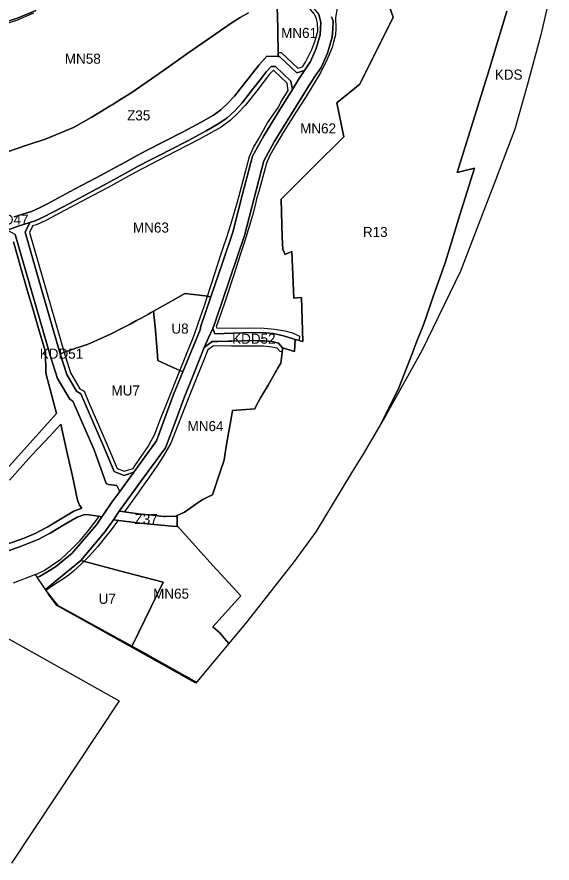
# Model space of a CAD drawing. Extents: x 7428841 to 7433518, y 5545054 to 5546840.
# Drawn here: x 7432924 to 7433454, y 5545245 to 5546085 of the extents above; entities that cross this region are included whole.
import ezdxf

# ---------------------------------------------------------------- set-up
doc = ezdxf.new("R2010")
doc.units = 0
for name, color, linetype in [('linie_rozgraniczajace', 7, 'Continuous'), ('linie_zabudowy_nieprzekraczalne', 7, 'Continuous'), ('oznaczenia_przeznaczen', 7, 'Continuous')]:
    doc.layers.add(name, color=color, linetype=linetype)

msp = doc.modelspace()

# ---------------------------------------------------------------- linework, layer by layer
at = {"layer": 'linie_rozgraniczajace'}
for points in [[(7433454.3, 5546115.72), (7433443.19, 5546066.88), (7433429.63, 5546016.49), (7433417.27, 5545973.13), (7433398.05, 5545922.73), (7433363.46, 5545832.41), (7433325.3, 5545753.97), (7433290.23, 5545690.46), (7433285.41, 5545682.3), (7433302.34, 5545716.55), (7433314.27, 5545746.9), (7433320.28, 5545762.8), (7433326.2, 5545777.24), (7433328.95, 5545785.66), (7433335.99, 5545806.26), (7433348.47, 5545841.54), (7433362.88, 5545888.07), (7433377.29, 5545934.6), (7433360.23, 5545930.2), (7433374.37, 5545975.87), (7433391.5, 5546031.17), (7433400.97, 5546061.74), (7433409.6, 5546090.32)], [(7433181.74, 5546094.87), (7433182.26, 5546073.37), (7433182.64, 5546045.32), (7433171.51, 5546045.51), (7433163.49, 5546036.88), (7433150.31, 5546019.98), (7433139.24, 5546005.8), (7433132.53, 5545998.52), (7433125.84, 5545992.31), (7433118.43, 5545987.1), (7433106.43, 5545980.19), (7433088.4, 5545970.56), (7433070.16, 5545961.15), (7433051.49, 5545951.53), (7433039.13, 5545945.15), (7433030.77, 5545940.55), (7433021.62, 5545935.53), (7433007.22, 5545927.61), (7432975.83, 5545910.91), (7432953.83, 5545899.22), (7432946.61, 5545895.38), (7432937.92, 5545891.47), (7432920.69, 5545886.06)], [(7433409.6, 5546090.32), (7433400.97, 5546061.74), (7433391.5, 5546031.17), (7433374.37, 5545975.87), (7433360.23, 5545930.2), (7433377.29, 5545934.6), (7433362.88, 5545888.07), (7433348.47, 5545841.54), (7433335.99, 5545806.26), (7433328.95, 5545785.66), (7433326.2, 5545777.24), (7433320.28, 5545762.8), (7433314.27, 5545746.9), (7433302.34, 5545716.55), (7433285.41, 5545682.3), (7433267.11, 5545651.33), (7433255.38, 5545631.97), (7433220.04, 5545573.5), (7433198.54, 5545544.11), (7433151.43, 5545484.12), (7433133.63, 5545462.68), (7433129.14, 5545467.92), (7433124.66, 5545473.16), (7433118, 5545479.19), (7433145.55, 5545510.1), (7433117.88, 5545540.1), (7433103.27, 5545556.46), (7433082.99, 5545578.82), (7433082.39, 5545578.86), (7433082.56, 5545589.65), (7433089.8, 5545593.1), (7433098.8, 5545599.43), (7433103.3, 5545602.59), (7433107.8, 5545605.75), (7433112.61, 5545608.07), (7433117.43, 5545610.39), (7433125.35, 5545633.94), (7433128.65, 5545643.77), (7433128.92, 5545644.9), (7433131.19, 5545658.13), (7433133.46, 5545671.37), (7433135.62, 5545683.94), (7433137.36, 5545694.08), (7433159.36, 5545695.62), (7433160.41, 5545698.08), (7433165.26, 5545706.45), (7433172.71, 5545719.26), (7433180.15, 5545732.08), (7433181.14, 5545733.79), (7433182.13, 5545735.49), (7433185.37, 5545740.86), (7433186.45, 5545751.57), (7433186.9, 5545756.06), (7433198.7, 5545752.45), (7433199.64, 5545764.59), (7433207.09, 5545762.29), (7433206.38, 5545784.21), (7433205.66, 5545806.13), (7433198.05, 5545805.51), (7433196.13, 5545851.62), (7433193.15, 5545850.35), (7433190.71, 5545849.47), (7433189.29, 5545848.96), (7433189.14, 5545849.48), (7433187.38, 5545854.17), (7433186.46, 5545865.63), (7433185.67, 5545903.81), (7433216.66, 5545934.69), (7433247.64, 5545965.57), (7433240.95, 5545999.33), (7433263.56, 5546017.81), (7433296.79, 5546084.2), (7433292.83, 5546095.75)], [(7433292.83, 5546095.75), (7433296.79, 5546084.2), (7433263.56, 5546017.81), (7433240.95, 5545999.33), (7433247.64, 5545965.57), (7433216.66, 5545934.69), (7433185.67, 5545903.81), (7433186.46, 5545865.63), (7433187.38, 5545854.17), (7433189.14, 5545849.48), (7433189.29, 5545848.96), (7433190.71, 5545849.47), (7433193.15, 5545850.35), (7433196.13, 5545851.62), (7433198.05, 5545805.51), (7433205.66, 5545806.13), (7433206.38, 5545784.21), (7433207.09, 5545762.29), (7433199.64, 5545764.59), (7433197.53, 5545765.25), (7433187.98, 5545768.2), (7433177.87, 5545770.29), (7433169.99, 5545771.04), (7433156.36, 5545771.31), (7433119.66, 5545769.97), (7433117.78, 5545775.22), (7433120.25, 5545781.48), (7433134.73, 5545824.55), (7433149.21, 5545867.63), (7433158.77, 5545904.72), (7433168.34, 5545941.82), (7433178.63, 5545960.65), (7433195.85, 5545988.42), (7433213.07, 5546016.2), (7433219.11, 5546025.37), (7433225.15, 5546034.53), (7433231.55, 5546048.59), (7433233.94, 5546056.61), (7433236.33, 5546064.63), (7433236.77, 5546072.71), (7433237.21, 5546080.78), (7433235.57, 5546084.76)], [(7432942.31, 5546090.87), (7432924.89, 5546083.84), (7432898.36, 5546074.96), (7432879.11, 5546070.63), (7432871.18, 5546069.83), (7432867.06, 5546069.26), (7432858.66, 5546068.83), (7432850.43, 5546069.48), (7432833.4, 5546070.19), (7432815.67, 5546072.58), (7432799.51, 5546076.76), (7432795.3, 5546077.85), (7432780.74, 5546084.48), (7432774.59, 5546087.28)], [(7432898.36, 5546074.96), (7432924.89, 5546083.84), (7432942.31, 5546090.87)], [(7433153.11, 5546088.58), (7433145.11, 5546083.9), (7433137.12, 5546079.23), (7433127.33, 5546072.35), (7433117.55, 5546065.47), (7433093.16, 5546048.49), (7433068.77, 5546031.51), (7433036.55, 5546008.95), (7433027.31, 5546003.19), (7433018.06, 5545997.44), (7433016.72, 5545996.64), (7433006.28, 5545990.38), (7432997.17, 5545984.93), (7432979.51, 5545974.82), (7432952.58, 5545963.64), (7432933.34, 5545957.17), (7432914.09, 5545950.7)], [(7432914.09, 5545950.7), (7432933.34, 5545957.17), (7432952.58, 5545963.64), (7432979.51, 5545974.82), (7432997.17, 5545984.93), (7433006.28, 5545990.38), (7433016.72, 5545996.64), (7433018.06, 5545997.44), (7433027.31, 5546003.19), (7433036.55, 5546008.95), (7433068.77, 5546031.51), (7433093.16, 5546048.49), (7433117.55, 5546065.47), (7433127.33, 5546072.35), (7433137.12, 5546079.23), (7433145.11, 5546083.9), (7433153.11, 5546088.58)], [(7433235.57, 5546084.76), (7433237.21, 5546080.78), (7433236.77, 5546072.71), (7433236.33, 5546064.63), (7433233.94, 5546056.61), (7433231.55, 5546048.59), (7433225.15, 5546034.53), (7433219.11, 5546025.37), (7433213.07, 5546016.2), (7433195.85, 5545988.42), (7433178.63, 5545960.65), (7433168.34, 5545941.82), (7433158.77, 5545904.72), (7433149.21, 5545867.63), (7433134.73, 5545824.55), (7433120.25, 5545781.48), (7433117.78, 5545775.22), (7433113.56, 5545765.93), (7433109.35, 5545756.63), (7433099.29, 5545731.19), (7433089.23, 5545705.76), (7433080.1, 5545681.4), (7433070.96, 5545657.04), (7433048.86, 5545626.81), (7433026.76, 5545596.58), (7433024.98, 5545593.99), (7433019.17, 5545585.48), (7433011.14, 5545573.75), (7432986.79, 5545544.92), (7432951.75, 5545516.36), (7432943.55, 5545528.46), (7432945.95, 5545529.2), (7432949.87, 5545531.68), (7432961.87, 5545538.78), (7432978.37, 5545552.3), (7433002.39, 5545580.44), (7433007.88, 5545588.47), (7433010.08, 5545591.69), (7433017.77, 5545602.93), (7433025.51, 5545613.51), (7433039.48, 5545632.62), (7433062.11, 5545663.9), (7433078.97, 5545709.72), (7433088.22, 5545732.35), (7433092.1, 5545741.83), (7433105.24, 5545773.95), (7433105.78, 5545777.76), (7433115.95, 5545806.93), (7433127.47, 5545840.48), (7433137.7, 5545871.04), (7433147.39, 5545908.65), (7433157.09, 5545946.26), (7433168.26, 5545966.69), (7433185.61, 5545994.68), (7433196.7, 5546012.57), (7433202.96, 5546022.66), (7433208.79, 5546031.51), (7433214.62, 5546040.35), (7433220.45, 5546053.25), (7433224.43, 5546066.7), (7433225.12, 5546079.37)], [(7433225.12, 5546079.37), (7433222.89, 5546086.94)], [(7432920.69, 5545886.06), (7432937.92, 5545891.47), (7432946.61, 5545895.38), (7432953.83, 5545899.22), (7432975.83, 5545910.91), (7433007.22, 5545927.61), (7433021.62, 5545935.53), (7433030.77, 5545940.55), (7433039.13, 5545945.15), (7433051.49, 5545951.53), (7433070.16, 5545961.15), (7433088.4, 5545970.56), (7433106.43, 5545980.19), (7433118.43, 5545987.1), (7433125.84, 5545992.31), (7433132.53, 5545998.52), (7433139.24, 5546005.8), (7433150.31, 5546019.98), (7433163.49, 5546036.88), (7433171.51, 5546045.51), (7433182.64, 5546045.32), (7433184.08, 5546045.29), (7433201.04, 5546029.2), (7433208.79, 5546031.51), (7433202.96, 5546022.66), (7433196.7, 5546012.57), (7433195.12, 5546020.98), (7433180.01, 5546035.37), (7433175.8, 5546035.44), (7433171.11, 5546030.39), (7433164.65, 5546022.11), (7433158.19, 5546013.83), (7433146.87, 5545999.32), (7433139.62, 5545991.45), (7433132.14, 5545984.52), (7433123.81, 5545978.66), (7433111.29, 5545971.45), (7433093.05, 5545961.7), (7433074.74, 5545952.26), (7433065.41, 5545947.45), (7433056.07, 5545942.64), (7433043.83, 5545936.33), (7433035.59, 5545931.79), (7433026.44, 5545926.76), (7433011.98, 5545918.81), (7432980.52, 5545902.08), (7432969.53, 5545896.24), (7432958.53, 5545890.39), (7432951.02, 5545886.39), (7432941.48, 5545882.1), (7432936.22, 5545880.45), (7432923.9, 5545876.59), (7432913.81, 5545872.91)], [(7432921.87, 5545868.65), (7432956.87, 5545747.44), (7432963.81, 5545725.63), (7432975.91, 5545705.16), (7432979.02, 5545703.38), (7433000.13, 5545654.83), (7433012.2, 5545621.38), (7433014.46, 5545620.66), (7433022.56, 5545619.44), (7433025.51, 5545613.51), (7433017.77, 5545602.93), (7433010.08, 5545591.69), (7433007.88, 5545588.47), (7433004.52, 5545589.05), (7432999.57, 5545589.89), (7432995.2, 5545590.28), (7432990.83, 5545590.68), (7432983.16, 5545588.16)], [(7432920.2, 5545861.37), (7432924.46, 5545846.25), (7432927.2, 5545836.48), (7432934.14, 5545812.44), (7432939.61, 5545793.76), (7432945.7, 5545773.1), (7432951.79, 5545752.1), (7432952.32, 5545730.87), (7432962.85, 5545690.82), (7432927.6, 5545652.07), (7432907.88, 5545629.63)], [(7432907.88, 5545629.63), (7432927.6, 5545652.07), (7432962.85, 5545690.82), (7432952.32, 5545730.87), (7432951.79, 5545752.1), (7432945.7, 5545773.1), (7432939.61, 5545793.76), (7432934.14, 5545812.44), (7432927.2, 5545836.48), (7432924.46, 5545846.25), (7432920.2, 5545861.37)], [(7432916.18, 5545624.85), (7432938.12, 5545649.21), (7432956.06, 5545668.58), (7432966.97, 5545680.5), (7432972.75, 5545654.7), (7432978.54, 5545628.89), (7432983.72, 5545604.84), (7432985.47, 5545600.05), (7432987.9, 5545596.86), (7432980.03, 5545593.9), (7432961.84, 5545583.01), (7432954.33, 5545578.53), (7432952.8, 5545577.74), (7432945.85, 5545574.18), (7432942.34, 5545572.06), (7432930.83, 5545567.34), (7432929.57, 5545566.82), (7432892.02, 5545553.66)], [(7432892.02, 5545553.66), (7432929.57, 5545566.82), (7432930.83, 5545567.34), (7432942.34, 5545572.06), (7432945.85, 5545574.18), (7432952.8, 5545577.74), (7432954.33, 5545578.53), (7432961.84, 5545583.01), (7432980.03, 5545593.9), (7432987.9, 5545596.86), (7432985.47, 5545600.05), (7432983.72, 5545604.84), (7432978.54, 5545628.89), (7432972.75, 5545654.7), (7432966.97, 5545680.5), (7432956.06, 5545668.58), (7432938.12, 5545649.21), (7432916.18, 5545624.85)], [(7432899.11, 5545549.06), (7432927.07, 5545559.08), (7432945.36, 5545566.21), (7432952.39, 5545570.2), (7432956.35, 5545572.35), (7432964.27, 5545576.97), (7432970.73, 5545580.8), (7432983.16, 5545588.16), (7432990.83, 5545590.68), (7432995.2, 5545590.28), (7432999.57, 5545589.89), (7433004.52, 5545589.05), (7433007.88, 5545588.47), (7433002.39, 5545580.44), (7432978.37, 5545552.3), (7432961.87, 5545538.78), (7432949.87, 5545531.68), (7432945.95, 5545529.2), (7432943.55, 5545528.46), (7432941.79, 5545531.05), (7432919.93, 5545522.54)], [(7432983.16, 5545588.16), (7432970.73, 5545580.8), (7432964.27, 5545576.97), (7432956.35, 5545572.35), (7432952.39, 5545570.2), (7432945.36, 5545566.21), (7432927.07, 5545559.08), (7432899.11, 5545549.06)], [(7432913.46, 5545468.42), (7433024.89, 5545405.88), (7432918.2, 5545244.76)]]:
    msp.add_lwpolyline(points, dxfattribs=at)
for points in [[(7433182.64, 5546045.32), (7433182.26, 5546073.37), (7433181.74, 5546094.87), (7433181.68, 5546097.34), (7433206.42, 5546104.28), (7433212.43, 5546099.54), (7433222.89, 5546086.94), (7433225.12, 5546079.37), (7433224.43, 5546066.7), (7433220.45, 5546053.25), (7433214.62, 5546040.35), (7433208.79, 5546031.51), (7433201.04, 5546029.2), (7433184.08, 5546045.29)], [(7432931.59, 5545870.85), (7432936.22, 5545880.45), (7432941.48, 5545882.1), (7432951.02, 5545886.39), (7432958.53, 5545890.39), (7432969.53, 5545896.24), (7432980.52, 5545902.08), (7433011.98, 5545918.81), (7433026.44, 5545926.76), (7433035.59, 5545931.79), (7433043.83, 5545936.33), (7433056.07, 5545942.64), (7433065.41, 5545947.45), (7433074.74, 5545952.26), (7433093.05, 5545961.7), (7433111.29, 5545971.45), (7433123.81, 5545978.66), (7433132.14, 5545984.52), (7433139.62, 5545991.45), (7433146.87, 5545999.32), (7433158.19, 5546013.83), (7433164.65, 5546022.11), (7433171.11, 5546030.39), (7433175.8, 5546035.44), (7433180.01, 5546035.37), (7433195.12, 5546020.98), (7433196.7, 5546012.57), (7433185.61, 5545994.68), (7433168.26, 5545966.69), (7433157.09, 5545946.26), (7433147.39, 5545908.65), (7433137.7, 5545871.04), (7433127.47, 5545840.48), (7433115.95, 5545806.93), (7433110.07, 5545807.65), (7433090.08, 5545809.96), (7433081.57, 5545805.11), (7433073.32, 5545800.5), (7433065.07, 5545795.89), (7433059.08, 5545792.55), (7433056.73, 5545791.13), (7433053.88, 5545789.57), (7433046.63, 5545785.63), (7433042.23, 5545783.25), (7433035.77, 5545779.75), (7433029.32, 5545776.25), (7433016.2, 5545769.74), (7433006.78, 5545765.41), (7432996.45, 5545760.9), (7432995.71, 5545760.6), (7432992.05, 5545759.23), (7432988.4, 5545757.85), (7432982, 5545755.67), (7432975.59, 5545753.49), (7432966.44, 5545750.35), (7432949.02, 5545810.6)], [(7432913.81, 5545872.91), (7432923.9, 5545876.59), (7432936.22, 5545880.45), (7432931.59, 5545870.85), (7432949.02, 5545810.6), (7432966.44, 5545750.35), (7432973, 5545729.74), (7432982.59, 5545713.04), (7432986.98, 5545710.36), (7433009.42, 5545658.54), (7433019.91, 5545633.44), (7433029.91, 5545629.41), (7433039.48, 5545632.62), (7433025.51, 5545613.51), (7433022.56, 5545619.44), (7433014.46, 5545620.66), (7433012.2, 5545621.38), (7433000.13, 5545654.83), (7432979.02, 5545703.38), (7432975.91, 5545705.16), (7432963.81, 5545725.63), (7432956.87, 5545747.44), (7432921.87, 5545868.65)], [(7433059.08, 5545792.55), (7433065.07, 5545795.89), (7433073.32, 5545800.5), (7433081.57, 5545805.11), (7433090.08, 5545809.96), (7433110.07, 5545807.65), (7433115.95, 5545806.93), (7433105.78, 5545777.76), (7433105.24, 5545773.95), (7433092.1, 5545741.83), (7433088.22, 5545732.35), (7433076.31, 5545737.73), (7433063.37, 5545743.58), (7433063, 5545748.62), (7433060.82, 5545773.81)], [(7432966.44, 5545750.35), (7432975.59, 5545753.49), (7432982, 5545755.67), (7432988.4, 5545757.85), (7432992.05, 5545759.23), (7432995.71, 5545760.6), (7432996.45, 5545760.9), (7433006.78, 5545765.41), (7433016.2, 5545769.74), (7433029.32, 5545776.25), (7433035.77, 5545779.75), (7433042.23, 5545783.25), (7433046.63, 5545785.63), (7433053.88, 5545789.57), (7433056.73, 5545791.13), (7433059.08, 5545792.55), (7433060.82, 5545773.81), (7433063, 5545748.62), (7433063.37, 5545743.58), (7433076.31, 5545737.73), (7433088.22, 5545732.35), (7433078.97, 5545709.72), (7433062.11, 5545663.9), (7433039.48, 5545632.62), (7433029.91, 5545629.41), (7433019.91, 5545633.44), (7433009.42, 5545658.54), (7432986.98, 5545710.36), (7432982.59, 5545713.04), (7432973, 5545729.74)], [(7433109.35, 5545756.63), (7433113.56, 5545765.93), (7433117.78, 5545775.22), (7433119.66, 5545769.97), (7433156.36, 5545771.31), (7433169.99, 5545771.04), (7433177.87, 5545770.29), (7433187.98, 5545768.2), (7433197.53, 5545765.25), (7433199.64, 5545764.59), (7433198.7, 5545752.45), (7433186.9, 5545756.06), (7433182.83, 5545760.73), (7433176.68, 5545762.37), (7433169.53, 5545763.04), (7433162.98, 5545763.18), (7433156.44, 5545763.31), (7433136.74, 5545762.78), (7433132.96, 5545762.76), (7433122.41, 5545762.48), (7433117.11, 5545762.34)], [(7433024.98, 5545593.99), (7433026.76, 5545596.58), (7433048.86, 5545626.81), (7433070.96, 5545657.04), (7433080.1, 5545681.4), (7433089.23, 5545705.76), (7433099.29, 5545731.19), (7433109.35, 5545756.63), (7433117.11, 5545762.34), (7433122.41, 5545762.48), (7433132.96, 5545762.76), (7433136.74, 5545762.78), (7433156.44, 5545763.31), (7433162.98, 5545763.18), (7433169.53, 5545763.04), (7433176.68, 5545762.37), (7433182.83, 5545760.73), (7433186.9, 5545756.06), (7433186.45, 5545751.57), (7433185.37, 5545740.86), (7433182.13, 5545735.49), (7433181.14, 5545733.79), (7433180.15, 5545732.08), (7433172.71, 5545719.26), (7433165.26, 5545706.45), (7433160.41, 5545698.08), (7433159.36, 5545695.62), (7433137.36, 5545694.08), (7433135.62, 5545683.94), (7433133.46, 5545671.37), (7433131.19, 5545658.13), (7433128.92, 5545644.9), (7433128.65, 5545643.77), (7433125.35, 5545633.94), (7433117.43, 5545610.39), (7433112.61, 5545608.07), (7433107.8, 5545605.75), (7433103.3, 5545602.59), (7433098.8, 5545599.43), (7433089.8, 5545593.1), (7433082.56, 5545589.65), (7433081.38, 5545589.09), (7433070.64, 5545588.68), (7433069.1, 5545588.84), (7433055.06, 5545590.27), (7433046.89, 5545591.11), (7433036.88, 5545592.43), (7433025.57, 5545593.91)], [(7433019.17, 5545585.48), (7433024.98, 5545593.99), (7433025.57, 5545593.91), (7433036.88, 5545592.43), (7433046.89, 5545591.11), (7433055.06, 5545590.27), (7433069.1, 5545588.84), (7433070.64, 5545588.68), (7433081.38, 5545589.09), (7433082.56, 5545589.65), (7433082.39, 5545578.86), (7433077.01, 5545579.31), (7433045.68, 5545582)], [(7432986.79, 5545544.92), (7433011.14, 5545573.75), (7433019.17, 5545585.48), (7433045.68, 5545582), (7433077.01, 5545579.31), (7433082.39, 5545578.86), (7433082.99, 5545578.82), (7433103.27, 5545556.46), (7433117.88, 5545540.1), (7433145.55, 5545510.1), (7433118, 5545479.19), (7433124.66, 5545473.16), (7433129.14, 5545467.92), (7433133.63, 5545462.68), (7433102.13, 5545424.75), (7433100.94, 5545423.3), (7433037.04, 5545459.04), (7433037.4, 5545459.78), (7433044.08, 5545473.26), (7433068.66, 5545523.51), (7433032.78, 5545532.85)], [(7432951.75, 5545516.36), (7432986.79, 5545544.92), (7433032.78, 5545532.85), (7433068.66, 5545523.51), (7433044.08, 5545473.26), (7433037.4, 5545459.78), (7433037.04, 5545459.04), (7432963.08, 5545500.41), (7432956.2, 5545509.79)]]:
    msp.add_lwpolyline(points, close=True, dxfattribs=at)
at = {"layer": 'linie_zabudowy_nieprzekraczalne'}
for points in [[(7433342.32, 5546243.08), (7433339.67, 5546241.2), (7433337.66, 5546239.17), (7433331.93, 5546230.99), (7433320.87, 5546214.93), (7433316.52, 5546208.86), (7433308.32, 5546200.49), (7433301.9, 5546193.06), (7433281.77, 5546159.01), (7433270.55, 5546138.07), (7433259.5, 5546117.66), (7433241.25, 5546093.66), (7433239.56, 5546083.82)], [(7433206.67, 5546035.14), (7433209.68, 5546039.7), (7433215.97, 5546052.31), (7433219.17, 5546060.17), (7433222.04, 5546070.56), (7433221.79, 5546078.88), (7433220.67, 5546082.57), (7433218.66, 5546087.35), (7433214.86, 5546091.94), (7433209.62, 5546097.67), (7433203.08, 5546103.37)], [(7432940.13, 5546088.26), (7432923.27, 5546081.18), (7432905.94, 5546075.63), (7432895.54, 5546072.28), (7432889.7, 5546070.44), (7432884.6, 5546069.46), (7432879.5, 5546068.48), (7432874.69, 5546067.96)], [(7433239.56, 5546083.82), (7433239.65, 5546081.03), (7433239.79, 5546076.27), (7433239.9, 5546073.38), (7433239.52, 5546066.85), (7433237.46, 5546059.42), (7433236.26, 5546054.38), (7433231.31, 5546042.56), (7433225.12, 5546029.83), (7433209.6, 5546004.57), (7433200.6, 5545990.49), (7433187.59, 5545969.99), (7433180.91, 5545958.52), (7433174.22, 5545947.05), (7433171.21, 5545939.55), (7433168.32, 5545929.48), (7433163.53, 5545911.47), (7433161.31, 5545903.95), (7433160.19, 5545899.25), (7433157.06, 5545887.53), (7433149.42, 5545862.3), (7433145.58, 5545850.56), (7433142.61, 5545841.35), (7433139.52, 5545831.65), (7433129.85, 5545801.59), (7433126.53, 5545791.74), (7433122.31, 5545780.49), (7433121.23, 5545777.36), (7433121.23, 5545777.36)], [(7433182.48, 5546049.32), (7433185.64, 5546049.44), (7433202.12, 5546033.7), (7433206.62, 5546035.04)], [(7433192.69, 5546011.69), (7433191.42, 5546018.97), (7433178.38, 5546031.39), (7433177.52, 5546031.41), (7433174.16, 5546027.79), (7433161.35, 5546011.37), (7433149.93, 5545996.73), (7433142.45, 5545988.63), (7433135.19, 5545981.89), (7433125.96, 5545975.28), (7433104.07, 5545963.05), (7433071.91, 5545946.3), (7433040.81, 5545930.27), (7433013.89, 5545915.3), (7432998.13, 5545906.92), (7432965.91, 5545889.78), (7432952.78, 5545882.8), (7432942.91, 5545878.36), (7432938.91, 5545877.1)], [(7433038.85, 5545636.45), (7433040.6, 5545639.03), (7433053.7, 5545658.36), (7433056.74, 5545663.79), (7433059.79, 5545669.22), (7433060.69, 5545671.52), (7433065.73, 5545684.65), (7433073.8, 5545705.13), (7433084.17, 5545730.95), (7433099.33, 5545768.68), (7433103.33, 5545780.24), (7433109.46, 5545798.03), (7433126.24, 5545849.3), (7433128.15, 5545855.37), (7433131.99, 5545867.13), (7433136.71, 5545881.85), (7433142.15, 5545901.22), (7433146.12, 5545916.06), (7433151.09, 5545934.7), (7433154.28, 5545945.95), (7433158.01, 5545954.98), (7433163.04, 5545963.22), (7433172.22, 5545979.35), (7433182.9, 5545994.88), (7433185.24, 5545999.87), (7433192.69, 5546011.69)], [(7432939.01, 5545877.02), (7432935.86, 5545870.49), (7432970.27, 5545751.51), (7432976.67, 5545731.38), (7432986.07, 5545715.48), (7432990.17, 5545713.15), (7432994.48, 5545702.53), (7433013.13, 5545660.02), (7433022.95, 5545636.52), (7433030.04, 5545633.67), (7433038.85, 5545636.45)], [(7433121.23, 5545777.36), (7433121.84, 5545776.04), (7433137.75, 5545775.69), (7433154.22, 5545775.85), (7433168.84, 5545775.67), (7433178.88, 5545774.79), (7433189.23, 5545772.91), (7433196.99, 5545771.07), (7433203.91, 5545767.87), (7433203.56, 5545763.3)], [(7433186.33, 5545752.05), (7433184.55, 5545752.6), (7433181.69, 5545755.93), (7433176.5, 5545756.93), (7433167.94, 5545757.68), (7433154.2, 5545757.85), (7433136.49, 5545757.67), (7433118.62, 5545758.1), (7433112.9, 5545754.22)], [(7433112.9, 5545754.22), (7433109.25, 5545744.93), (7433100.03, 5545722.06), (7433094.06, 5545707.06), (7433083.18, 5545679.47), (7433076.13, 5545661.55), (7433072.57, 5545655.22), (7433069.02, 5545648.89), (7433062.19, 5545638.81), (7433054.03, 5545626.85), (7433051.33, 5545623.04), (7433042.68, 5545611.06), (7433029.81, 5545593.19)], [(7432942.37, 5545531.23), (7432950.54, 5545535.21), (7432967.03, 5545546.38), (7432977.74, 5545556.33), (7432986.27, 5545564.83), (7432994.63, 5545574.73), (7433004.98, 5545588.61), (7433005.22, 5545588.94)], [(7433023.92, 5545585.03), (7433023.18, 5545584), (7433015.94, 5545574.31), (7433014.06, 5545571.92), (7433003.57, 5545558.79), (7432995.49, 5545549.84), (7432987.96, 5545542.21), (7432979.57, 5545534.44), (7432975.63, 5545531.18), (7432969.68, 5545526.73), (7432960.8, 5545521.15), (7432952.36, 5545515.45)], [(7432952.36, 5545515.45), (7432963.9, 5545500.76), (7433047.97, 5545454.32), (7433101.58, 5545424.47)]]:
    msp.add_lwpolyline(points, dxfattribs=at)

# ---------------------------------------------------------------- texts
at = {"layer": 'oznaczenia_przeznaczen'}
for s, p in [('MN61', (7433185.53, 5546063.71)), ('MN58', (7432971.03, 5546038.13)), ('KDS', (7433397.52, 5546022.35)), ('Z35', (7433032.78, 5545981.88)), ('MN62', (7433204.41, 5545968.99)), ('KDD47', (7432891.92, 5545878.41)), ('MN63', (7433038.6, 5545870.56)), ('R13', (7433266.68, 5545866.16)), ('U8', (7433076.76, 5545770.24)), ('KDD52', (7433136.94, 5545760.21)), ('KDD51', (7432946.18, 5545745.35)), ('MU7', (7433017.23, 5545708.84)), ('MN64', (7433092.75, 5545673.45)), ('Z37', (7433040.16, 5545581.19)), ('MN65', (7433058.57, 5545507.15)), ('U7', (7433004.55, 5545502.09))]:
    msp.add_text(s, height=10, dxfattribs=at).set_placement(p)

doc.saveas('drawing.dxf')
